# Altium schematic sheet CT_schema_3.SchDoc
size 207 x 169 mm
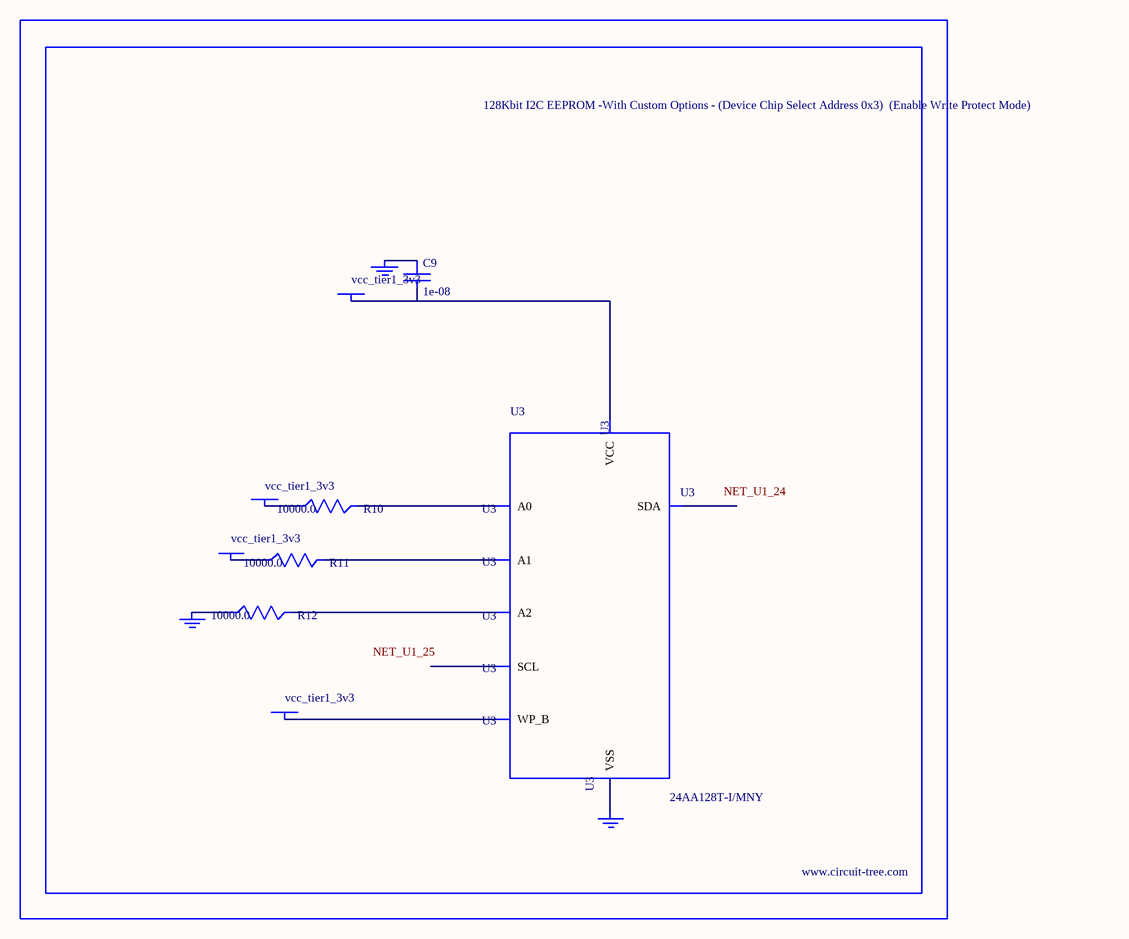
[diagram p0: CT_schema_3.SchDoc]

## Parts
BORDER2  (no value)
C9  1e-08  [C0402]
GND_INSTANCE_2_0  (no value)
GND_INSTANCE_2_1  (no value)
GND_INSTANCE_2_2  (no value)
POWER_INSTANCE_2_0  vcc_tier1_3v3
POWER_INSTANCE_2_1  vcc_tier1_3v3
POWER_INSTANCE_2_2  vcc_tier1_3v3
POWER_INSTANCE_2_3  vcc_tier1_3v3
R10  10000.0  [R0603]
R11  10000.0  [R0603]
R12  10000.0  [R0603]
U3  24AA128T-I/MNY  [TDFN-8/6MM]

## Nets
NetC9_1: C9.1 GND_INSTANCE_2_1.0(GND)
NetC9_2: C9.2 POWER_INSTANCE_2_3.0(PWR) U3.8(VCC)
NetGND_INSTANCE_2_0_0: GND_INSTANCE_2_0.0(GND) R12.1
NetGND_INSTANCE_2_2_0: GND_INSTANCE_2_2.0(GND) U3.4(VSS)
NetPOWER_INSTANCE_2_0_0: POWER_INSTANCE_2_0.0(PWR) R10.1
NetPOWER_INSTANCE_2_1_0: POWER_INSTANCE_2_1.0(PWR) R11.1
NetPOWER_INSTANCE_2_2_0: POWER_INSTANCE_2_2.0(PWR) U3.7(WP_B)
NetR10_2: R10.2 U3.1(A0)
NetR11_2: R11.2 U3.2(A1)
NetR12_2: R12.2 U3.3(A2)

Not connected (* = marked no-connect by the designer): U3 5(SDA) 6(SCL)

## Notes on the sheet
- Labels drawn without touching a wire or pin: NET_U1_24, NET_U1_25

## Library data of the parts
BORDER2 = BORDER_PAGE2
C9 = C0402C103K3RAC
GND_INSTANCE_2_0-GND_INSTANCE_2_2 = GND
POWER_INSTANCE_2_0-POWER_INSTANCE_2_3 = PWR
R10-R12 = RC0603JR-0710KL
